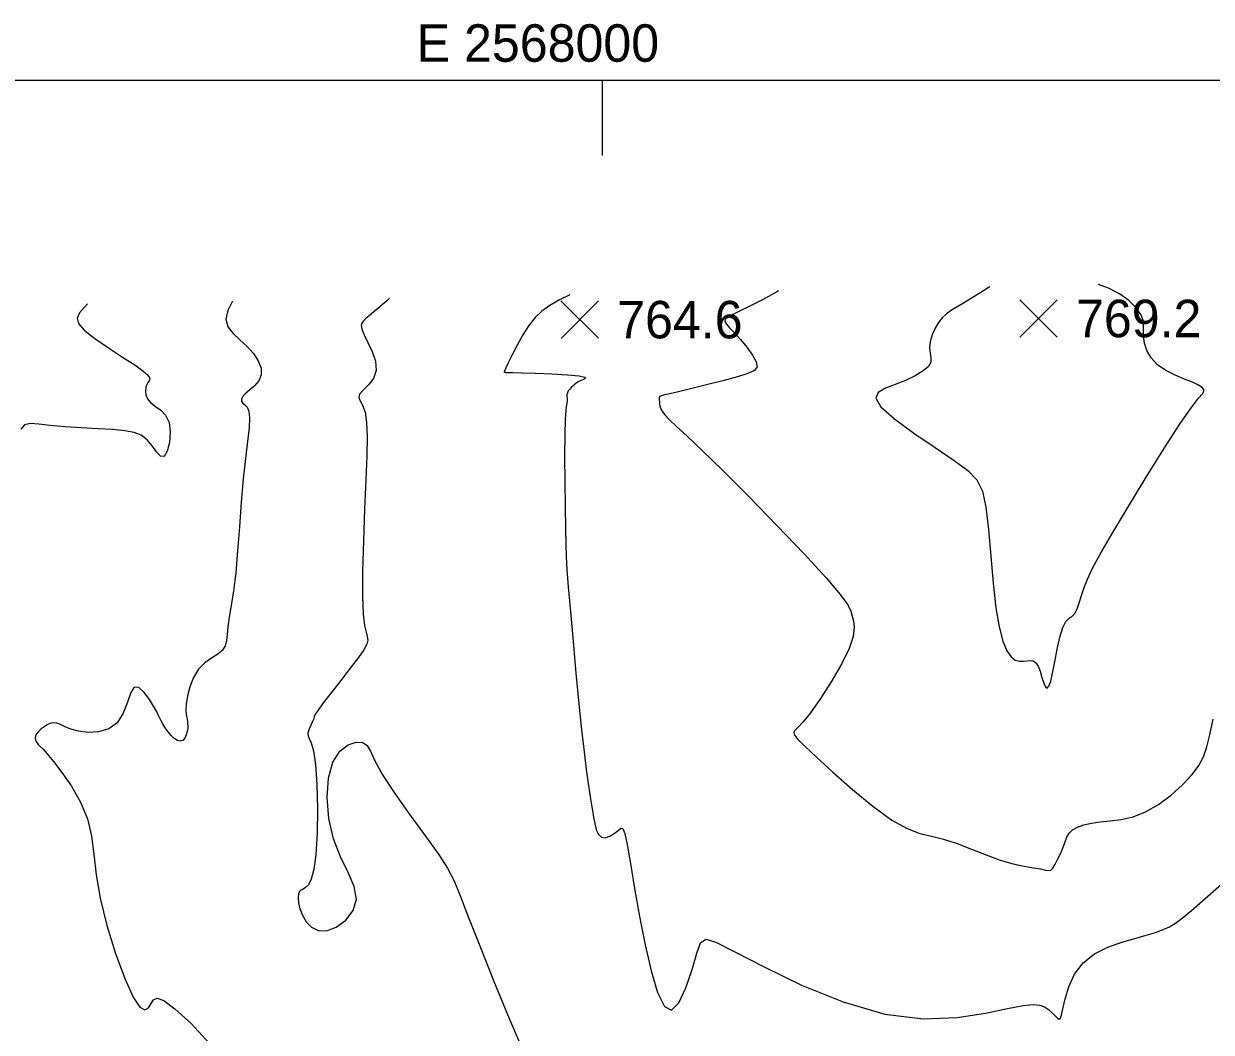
# Model space of a CAD drawing. Extents: x 2566142 to 2571431, y 418755 to 421584.
# Drawn here: x 2567768.3 to 2568243.6, y 421180.6 to 421584.4 of the extents above; entities that cross this region are included whole.
import ezdxf

# ---------------------------------------------------------------- set-up
doc = ezdxf.new("R2010")
doc.units = 0
for name, color, linetype in [('Contour_ADS_Major', 7, 'Continuous'), ('Contour_ADS_Minor', 7, 'Continuous'), ('Contour_ADS_Spot_Elevation', 7, 'Continuous'), ('Contour_ADS_State_Plane_Border', 7, 'Continuous')]:
    doc.layers.add(name, color=color, linetype=linetype)

# ---------------------------------------------------------------- blocks, each defined once
blk = doc.blocks.new('S750')
at = {"layer": 'Contour_ADS_Spot_Elevation'}
for p, q in [((-0.5, 0.498), (0.5, -0.498)), ((-0.498, -0.5), (0.498, 0.5))]:
    blk.add_line(p, q, dxfattribs=at)

msp = doc.modelspace()

# ---------------------------------------------------------------- linework, layer by layer
at = {"layer": 'Contour_ADS_Major'}
for points in [[(2567851.85, 421473.31), (2567849.96, 421469.6), (2567849.2, 421466.06), (2567850.03, 421463.01), (2567852.07, 421460.32), (2567854.81, 421457.78), (2567857.68, 421455.18), (2567860.22, 421452.36), (2567862.15, 421449.42), (2567863.27, 421446.52), (2567863.37, 421443.82), (2567862.35, 421441.44), (2567860.61, 421439.4), (2567858.62, 421437.66), (2567856.9, 421436.2), (2567855.84, 421434.98), (2567855.41, 421433.97), (2567855.52, 421433.14), (2567856.03, 421432.45), (2567856.82, 421431.81), (2567857.67, 421430.88), (2567858.37, 421429.27), (2567858.69, 421426.6), (2567858.48, 421422.55), (2567857.85, 421417.08), (2567857, 421410.25), (2567856.11, 421402.1), (2567855.33, 421392.8), (2567854.62, 421382.95), (2567853.92, 421373.29), (2567853.14, 421364.54), (2567852.25, 421357.28), (2567851.34, 421351.42), (2567850.54, 421346.72), (2567849.98, 421342.95), (2567849.71, 421339.88), (2567849.48, 421337.37), (2567848.98, 421335.31), (2567847.86, 421333.57), (2567845.93, 421332.01), (2567843.44, 421330.39), (2567840.76, 421328.44), (2567838.27, 421325.9), (2567836.27, 421322.62), (2567834.79, 421318.92), (2567833.8, 421315.23), (2567833.26, 421311.99), (2567833.12, 421309.53), (2567833.26, 421307.78), (2567833.52, 421306.57), (2567833.75, 421305.73), (2567833.85, 421305.11), (2567833.84, 421304.65), (2567833.8, 421304.31), (2567833.79, 421304.06), (2567833.85, 421303.84), (2567833.95, 421303.54), (2567834.01, 421303.05), (2567833.96, 421302.22), (2567833.75, 421301.02), (2567833.35, 421299.63), (2567832.76, 421298.35), (2567831.96, 421297.45), (2567830.95, 421297.15), (2567829.8, 421297.42), (2567828.55, 421298.18), (2567827.29, 421299.36), (2567826.08, 421300.85), (2567824.96, 421302.49), (2567824, 421304.12), (2567823.24, 421305.53), (2567822.69, 421306.65), (2567822.17, 421307.73), (2567821.45, 421309.1), (2567820.31, 421311.1), (2567818.6, 421313.86), (2567816.55, 421316.67), (2567814.44, 421318.61), (2567812.57, 421318.77), (2567811.13, 421316.55), (2567809.8, 421312.71), (2567808.15, 421308.33), (2567805.75, 421304.48), (2567802.33, 421302.01), (2567798.26, 421300.84), (2567794.05, 421300.65), (2567790.23, 421301.12), (2567787.19, 421301.95), (2567784.87, 421302.92), (2567783.05, 421303.8), (2567781.54, 421304.39), (2567780.17, 421304.52), (2567778.88, 421304.24), (2567777.66, 421303.67), (2567776.48, 421302.91), (2567775.34, 421302.07), (2567774.32, 421301.17), (2567773.51, 421300.24), (2567773.01, 421299.3), (2567772.87, 421298.38), (2567773.06, 421297.48)], [(2567773.06, 421297.48), (2567773.51, 421296.63), (2567774.14, 421295.83), (2567774.92, 421295.04), (2567776.05, 421293.91), (2567777.74, 421292.04), (2567780.22, 421289.04), (2567783.59, 421284.63), (2567787.39, 421279.06), (2567791, 421272.72), (2567793.82, 421265.99), (2567795.47, 421259.12), (2567796.41, 421251.82), (2567797.32, 421243.65), (2567798.89, 421234.19), (2567801.58, 421223.32), (2567805.06, 421212.15), (2567808.77, 421202.09), (2567812.17, 421194.57), (2567814.82, 421190.61), (2567816.77, 421189.56), (2567818.2, 421190.39), (2567819.28, 421192.06), (2567820.27, 421193.57), (2567821.73, 421194.2), (2567824.34, 421193.24), (2567828.76, 421190), (2567835.26, 421184.06), (2567842.63, 421176.02)]]:
    msp.add_lwpolyline(points, dxfattribs=at)
at = {"layer": 'Contour_ADS_Minor'}
for points in [[(2568206.93, 421476.24), (2568202.46, 421478.56), (2568198.43, 421479.93)], [(2567986.83, 421475.89), (2567982.76, 421473.83), (2567978.88, 421471.63), (2567975.71, 421469.35), (2567973.01, 421466.75), (2567970.53, 421463.59), (2567968.09, 421459.76), (2567965.78, 421455.64), (2567963.78, 421451.75), (2567962.25, 421448.62), (2567961.3, 421446.62), (2567960.82, 421445.57), (2567960.65, 421445.15), (2567960.63, 421445.06), (2567960.62, 421445.03), (2567960.61, 421445), (2567960.63, 421444.97), (2567960.69, 421444.93), (2567960.8, 421444.88), (2567960.96, 421444.83), (2567961.12, 421444.8), (2567961.26, 421444.78), (2567961.47, 421444.79), (2567962.22, 421444.79), (2567964.08, 421444.76), (2567967.63, 421444.65), (2567973.15, 421444.45), (2567979.67, 421444.15), (2567985.92, 421443.78), (2567990.65, 421443.36), (2567992.92, 421442.9), (2567993.2, 421442.42), (2567992.29, 421441.93), (2567991, 421441.42), (2567989.97, 421440.91), (2567989.23, 421440.39), (2567988.65, 421439.84), (2567988.09, 421439.27), (2567987.47, 421438.67), (2567986.83, 421438.03), (2567986.27, 421437.36), (2567985.89, 421436.65), (2567985.74, 421435.92), (2567985.74, 421435.12), (2567985.78, 421434.22), (2567985.75, 421433.19), (2567985.56, 421431.89), (2567985.29, 421429.71), (2567985.01, 421425.95), (2567984.81, 421419.91), (2567984.76, 421411.25), (2567984.82, 421401.09), (2567984.96, 421390.91), (2567985.1, 421382.21), (2567985.23, 421375.95), (2567985.4, 421371.05), (2567985.72, 421365.92), (2567986.27, 421358.96), (2567987.11, 421349.05), (2567988.16, 421337.05), (2567989.33, 421324.3), (2567990.5, 421312.13), (2567991.59, 421301.64), (2567992.58, 421292.91), (2567993.46, 421285.79), (2567994.23, 421280.12), (2567994.88, 421275.7), (2567995.44, 421272.23), (2567995.95, 421269.35), (2567996.41, 421266.72), (2567996.89, 421264.1), (2567997.48, 421261.68), (2567998.31, 421259.75), (2567999.49, 421258.62), (2568001.08, 421258.47), (2568002.89, 421259.09), (2568004.68, 421260.15), (2568006.2, 421261.33), (2568007.29, 421262.23), (2568008.1, 421262.12), (2568008.86, 421260.21), (2568009.82, 421255.7), (2568011.14, 421248.1), (2568012.82, 421238.16), (2568014.81, 421226.97), (2568017.03, 421215.6), (2568019.44, 421205.1), (2568022.01, 421196.54), (2568024.72, 421190.94), (2568027.57, 421189.35), (2568030.49, 421192.32), (2568033.31, 421198.4), (2568035.8, 421205.67), (2568037.75, 421212.17), (2568039.2, 421216.31), (2568041.27, 421217.78), (2568045.36, 421216.61), (2568052.85, 421212.83), (2568064.64, 421206.7), (2568079.64, 421199.48), (2568096.28, 421192.69)], [(2568070.4, 421477.48), (2568069.69, 421477), (2568064.2, 421473.96), (2568058.88, 421471.3), (2568054.72, 421469.31), (2568051.79, 421467.88), (2568049.96, 421466.83), (2568049.05, 421465.98), (2568048.93, 421465.12), (2568049.54, 421464.08), (2568050.83, 421462.65), (2568052.75, 421460.63), (2568055.19, 421457.92), (2568057.77, 421454.83), (2568060.02, 421451.74), (2568061.49, 421449.06), (2568061.79, 421447.06), (2568060.72, 421445.57), (2568058.15, 421444.32), (2568053.94, 421443.01), (2568048.15, 421441.46), (2568041.55, 421439.78), (2568035.11, 421438.2), (2568029.77, 421436.91), (2568026.27, 421436.07), (2568024.35, 421435.61), (2568023.48, 421435.4), (2568023.18, 421435.3), (2568023.02, 421435.21), (2568022.9, 421435.12), (2568022.81, 421435.02), (2568022.75, 421434.93), (2568022.71, 421434.84), (2568022.69, 421434.72), (2568022.67, 421434.51), (2568022.67, 421434.16), (2568022.68, 421433.65), (2568022.71, 421432.98), (2568022.79, 421432.2), (2568022.94, 421431.35), (2568023.2, 421430.42), (2568023.77, 421429.3), (2568024.88, 421427.82), (2568026.73, 421425.83), (2568029.59, 421423.12), (2568033.82, 421419.2), (2568039.82, 421413.54), (2568047.98, 421405.6), (2568058.37, 421395.2), (2568069.77, 421383.53), (2568080.65, 421372.13), (2568089.47, 421362.54), (2568095.1, 421355.9), (2568098.09, 421351.72), (2568099.37, 421349.13), (2568099.92, 421347.22), (2568100.45, 421345.2), (2568100.72, 421342.61), (2568100.28, 421339.08), (2568098.65, 421334.24), (2568095.57, 421327.95), (2568091.51, 421320.93), (2568087.17, 421314.14), (2568083.21, 421308.53), (2568080.2, 421304.8), (2568078.15, 421302.61), (2568076.96, 421301.39), (2568076.52, 421300.55), (2568076.82, 421299.52), (2568078.16, 421297.84), (2568080.94, 421295.07), (2568085.55, 421290.75), (2568092.15, 421284.72), (2568100.03, 421277.78), (2568108.2, 421271.03), (2568115.71, 421265.54), (2568121.87, 421262.09), (2568126.99, 421260.19), (2568131.66, 421259.06), (2568136.46, 421257.9), (2568141.84, 421256.11), (2568147.63, 421253.88), (2568153.5, 421251.57), (2568159.14, 421249.53), (2568164.27, 421248.06), (2568168.75, 421247.08), (2568172.45, 421246.43), (2568175.29, 421245.94), (2568177.2, 421245.53), (2568178.45, 421245.32), (2568179.32, 421245.52), (2568180.13, 421246.33), (2568181.12, 421247.88), (2568182.23, 421249.97), (2568183.33, 421252.33), (2568184.31, 421254.68), (2568185.08, 421256.8), (2568185.82, 421258.65), (2568186.75, 421260.25), (2568188.09, 421261.61), (2568190.02, 421262.73)], [(2568154.94, 421479.1), (2568154.29, 421478.66), (2568151.43, 421476.84), (2568148.26, 421474.88), (2568145.05, 421472.94), (2568142.11, 421471.16), (2568139.65, 421469.64), (2568137.62, 421468.21), (2568135.92, 421466.67), (2568134.42, 421464.79), (2568133.06, 421462.43), (2568131.92, 421459.77), (2568131.14, 421457.07), (2568130.85, 421454.56), (2568131.06, 421452.44), (2568131.39, 421450.61), (2568131.34, 421448.92), (2568130.4, 421447.21), (2568128.23, 421445.36), (2568125.04, 421443.45), (2568121.21, 421441.6), (2568117.09, 421439.92), (2568113.15, 421438.44), (2568110.25, 421436.78), (2568109.32, 421434.46), (2568111.34, 421431.01), (2568116.81, 421426.17), (2568124.58, 421420.47), (2568133.06, 421414.67), (2568140.67, 421409.52), (2568146.19, 421405.46), (2568149.79, 421401.7), (2568152.02, 421397.17), (2568153.43, 421390.77), (2568154.5, 421381.82), (2568155.43, 421371.25), (2568156.34, 421360.39), (2568157.39, 421350.56), (2568158.67, 421342.84), (2568160.14, 421337.18), (2568161.76, 421333.28), (2568163.45, 421330.84), (2568165.15, 421329.55), (2568166.82, 421329.09), (2568168.41, 421329.13), (2568169.87, 421329.35), (2568171.17, 421329.46), (2568172.32, 421329.25), (2568173.34, 421328.55), (2568174.25, 421327.19), (2568175.08, 421325.09), (2568175.84, 421322.65), (2568176.55, 421320.39), (2568177.24, 421318.81), (2568177.91, 421318.35), (2568178.59, 421319.1), (2568179.32, 421321.12), (2568180.1, 421324.41), (2568180.97, 421328.89), (2568181.94, 421333.93), (2568182.99, 421338.76), (2568184.15, 421342.63), (2568185.39, 421345.01), (2568186.66, 421346.32), (2568187.88, 421347.19), (2568188.98, 421348.28), (2568189.93, 421350.08), (2568190.79, 421352.54), (2568191.67, 421355.45), (2568192.69, 421358.62), (2568194, 421362), (2568195.99, 421366.19), (2568199.1, 421371.94), (2568203.76, 421380.01), (2568210.16, 421390.72), (2568217.54, 421402.81), (2568224.9, 421414.57), (2568231.21, 421424.3), (2568235.72, 421430.76), (2568238.54, 421434.43), (2568240.07, 421436.25), (2568240.66, 421437.15), (2568240.62, 421437.93), (2568239.91, 421438.77), (2568238.43, 421439.72), (2568236.08, 421440.81), (2568232.86, 421442.1), (2568229.14, 421443.65), (2568225.38, 421445.54), (2568222.07, 421447.84), (2568219.56, 421450.56), (2568217.86, 421453.53), (2568216.85, 421456.5), (2568216.43, 421459.23), (2568216.44, 421461.56), (2568216.53, 421463.66), (2568216.32, 421465.74), (2568215.42, 421468.03), (2568213.52, 421470.69), (2568210.65, 421473.52), (2568206.93, 421476.24)], [(2567793.84, 421472.2), (2567792.66, 421470.95), (2567790.67, 421468.64), (2567789.72, 421466.56), (2567790.19, 421464.36), (2567792.47, 421461.69), (2567796.73, 421458.33), (2567802.19, 421454.6), (2567807.85, 421450.94), (2567812.72, 421447.77), (2567816.01, 421445.45), (2567817.86, 421443.86), (2567818.66, 421442.78), (2567818.75, 421442.02), (2567818.48, 421441.36), (2567818.03, 421440.69), (2567817.54, 421439.88), (2567817.15, 421438.82), (2567817.01, 421437.43), (2567817.22, 421435.83), (2567817.9, 421434.17), (2567819.16, 421432.6), (2567821.01, 421431.19), (2567823.13, 421429.66), (2567825.08, 421427.64), (2567826.45, 421424.78), (2567826.93, 421420.92), (2567826.61, 421416.75), (2567825.73, 421413.18), (2567824.49, 421411.13), (2567823.09, 421411.22), (2567821.51, 421412.91), (2567819.73, 421415.39), (2567817.71, 421417.84), (2567815.37, 421419.62), (2567812.48, 421420.75), (2567808.77, 421421.43), (2567803.97, 421421.87), (2567797.98, 421422.23), (2567791.33, 421422.59), (2567784.73, 421423), (2567778.89, 421423.52), (2567774.34, 421424.1), (2567771.01, 421424.36), (2567768.67, 421423.85), (2567767.09, 421422.09)], [(2567914.68, 421474.51), (2567913.79, 421473.62), (2567910.8, 421471.01), (2567908.39, 421468.97), (2567906.6, 421467.45), (2567905.29, 421466.31), (2567904.34, 421465.4), (2567903.68, 421464.56), (2567903.4, 421463.55), (2567903.63, 421462.08), (2567904.5, 421459.88), (2567906.04, 421456.8), (2567907.76, 421453.12), (2567909.06, 421449.23), (2567909.35, 421445.54), (2567908.24, 421442.37), (2567906.27, 421439.75), (2567904.17, 421437.64), (2567902.68, 421436), (2567902.36, 421434.72), (2567902.94, 421433.4), (2567903.95, 421431.6), (2567904.94, 421428.85), (2567905.54, 421424.74), (2567905.73, 421419), (2567905.6, 421411.4), (2567905.24, 421401.71), (2567904.75, 421389.99), (2567904.25, 421377.38), (2567903.9, 421365.3), (2567903.84, 421355.17), (2567904.16, 421348.04), (2567904.72, 421343.5), (2567905.33, 421340.76), (2567905.82, 421339.01), (2567905.98, 421337.55), (2567905.6, 421335.92), (2567904.44, 421333.73), (2567902.28, 421330.59), (2567899.02, 421326.3), (2567895.16, 421321.37), (2567891.33, 421316.51), (2567888.15, 421312.41), (2567886.1, 421309.59), (2567885.01, 421307.87), (2567884.55, 421306.9), (2567884.4, 421306.33), (2567884.27, 421305.84), (2567884.08, 421305.31), (2567883.81, 421304.67), (2567883.41, 421303.85), (2567882.9, 421302.81), (2567882.39, 421301.63), (2567882.08, 421300.41), (2567882.11, 421299.26), (2567882.6, 421298.14), (2567883.4, 421296.39), (2567884.3, 421293.21), (2567885.11, 421287.8), (2567885.63, 421279.72), (2567885.84, 421270.05), (2567885.71, 421260.24), (2567885.24, 421251.76), (2567884.44, 421245.7), (2567883.4, 421241.85), (2567882.25, 421239.63), (2567881.12, 421238.48), (2567880.11, 421237.87), (2567879.27, 421237.46), (2567878.63, 421236.94), (2567878.23, 421236.03), (2567878.1, 421234.49), (2567878.29, 421232.42), (2567878.87, 421229.99), (2567879.89, 421227.39), (2567881.41, 421224.82), (2567883.48, 421222.66), (2567886.16, 421221.33), (2567889.49, 421221.24), (2567893.4, 421222.69), (2567897.23, 421225.48), (2567900.19, 421229.32), (2567901.48, 421233.87), (2567900.58, 421238.91), (2567898.14, 421244.52), (2567895.05, 421250.86), (2567892.22, 421258.07), (2567890.41, 421266.17), (2567889.77, 421274.51), (2567890.31, 421282.28), (2567892.01, 421288.69), (2567894.78, 421293.1), (2567898.12, 421295.67), (2567901.42, 421296.71), (2567904.08, 421296.56), (2567905.75, 421295.42), (2567907.03, 421293.1), (2567908.79, 421289.28), (2567911.86, 421283.65), (2567916.81, 421276.14), (2567922.89, 421267.6)], [(2568190.02, 421262.73), (2568192.54, 421263.64), (2568195.6, 421264.34), (2568199.16, 421264.84), (2568203.15, 421265.22), (2568207.54, 421265.76), (2568212.28, 421266.82), (2568217.31, 421268.76), (2568222.53, 421271.78), (2568227.63, 421275.59), (2568232.24, 421279.73), (2568236, 421283.74), (2568238.66, 421287.36), (2568240.47, 421290.89), (2568241.78, 421294.85), (2568242.96, 421299.72), (2568244.37, 421305.97)], [(2567922.89, 421267.6), (2567929.07, 421259.13), (2567934.31, 421251.81), (2567937.9, 421246.29), (2567940.44, 421241.41), (2567942.87, 421235.57), (2567946.11, 421227.16), (2567950.8, 421215.22), (2567956.36, 421201.32), (2567961.95, 421187.66), (2567966.7, 421176.45)], [(2568096.28, 421192.69), (2568112.97, 421187.82), (2568128.35, 421185.95), (2568141.88, 421186.43), (2568153.23, 421188.17), (2568162.09, 421190.07), (2568168.3, 421191.27), (2568172.36, 421191.68), (2568174.97, 421191.46), (2568176.8, 421190.72), (2568178.41, 421189.63), (2568179.87, 421188.38), (2568181.11, 421187.18), (2568182.07, 421186.24), (2568182.71, 421185.78), (2568183.17, 421186.06), (2568183.62, 421187.35), (2568184.2, 421189.93), (2568185.11, 421193.9), (2568186.59, 421198.76), (2568188.89, 421203.82), (2568192.27, 421208.4), (2568196.85, 421211.97), (2568202.21, 421214.62), (2568207.8, 421216.59), (2568213.05, 421218.11), (2568217.51, 421219.38), (2568221.22, 421220.53), (2568224.3, 421221.65), (2568226.89, 421222.82), (2568229.22, 421224.2), (2568231.89, 421226.22), (2568235.62, 421229.38), (2568241.11, 421234.17), (2568248.74, 421240.86)]]:
    msp.add_lwpolyline(points, dxfattribs=at)
at = {"layer": 'Contour_ADS_State_Plane_Border'}
msp.add_line((2568000, 421531.67), (2568000, 421561.67), dxfattribs=at)
msp.add_lwpolyline([(2566164.43, 418777.5), (2571407.81, 418777.5), (2571407.81, 421561.67), (2566164.43, 421561.67), (2566164.43, 418777.5)], close=True, dxfattribs=at)

# ---------------------------------------------------------------- block references
at = {"layer": 'Contour_ADS_Spot_Elevation', "xscale": 15, "yscale": 15}
for p in [(2567990.82, 421465.91), (2568174.45, 421466.37)]:
    msp.add_blockref('S750', p, dxfattribs=at)

# ---------------------------------------------------------------- texts
at = {"layer": 'Contour_ADS_Spot_Elevation'}
for s, p in [('764.6', (2568005.82, 421458.41)), ('769.2', (2568189.45, 421458.87))]:
    msp.add_text(s, height=15, dxfattribs=at).set_placement(p)
at = {"layer": 'Contour_ADS_State_Plane_Border'}
msp.add_text(' E 2568000', height=15, dxfattribs=at).set_placement((2567920, 421569.17))

doc.saveas('drawing.dxf')
